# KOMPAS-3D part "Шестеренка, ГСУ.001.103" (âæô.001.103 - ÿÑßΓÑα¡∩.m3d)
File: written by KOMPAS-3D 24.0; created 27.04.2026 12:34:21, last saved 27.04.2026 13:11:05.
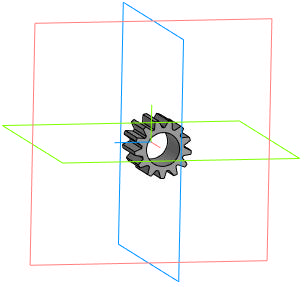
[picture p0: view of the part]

Document properties: Автор: User7; Полное имя файла: C:\Users\User7\Desktop\олимп\ГСУ.001.103 - Шестерня.m3d

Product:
- Part/product: Шестеренка  | designation ГСУ.001.103
    Масса: 0.003838

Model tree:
1. Эскиз:1
2. Элемент выдавливания:1
     Расстояние 1 = 10
3. Элемент выдавливания:2
     Расстояние 1 = 10
4. Массив по концентрической сетке:1  (with: Элемент выдавливания:2, Эскиз:1, Грань.Элемент выдавливания:1)  (13 pattern instances)
     Шаг 2 = 360

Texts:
  ГСУ.001.103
